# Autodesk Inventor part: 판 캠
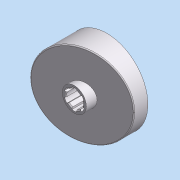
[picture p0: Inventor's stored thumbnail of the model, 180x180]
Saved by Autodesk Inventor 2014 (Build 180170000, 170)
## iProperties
Created: 2012-05
Part Number: 판 캠
Document SubType Name: 모델링
Designer: SeoGD™
Material: 강철
Density: 7.85 g/cm^3
Appearance: 알루미늄 - 평지
Mass: 681.587 g
Surface Area: 331.303 cm^2
Volume: 86.8264 cm^3
변환 표준: STEP AP214IS
파일 이름: C:\Users\SeoGD\Desktop\?쒗뿕\??stp
전처리기: Build: 253, Release: 2010 SP1 - Date: Wed 07/29/2009
전송 단위: 밀리미터
불확실성: 0.01
Author: SeoGD™
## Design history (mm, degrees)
node "작업 평면4"
sketch "스케치1"
  geometry: C1 r 44.5 at (0, 0); 1 further point
  constraints: 1 centre point, 1 coincident
  dimensions: "d25" = 89 diameter of C1
extrude "돌출1" new body sketch "스케치1" distance "d1" = 40; taper "d2" = 0 deg
sketch "스케치2"
  geometry: L1 (-44.5, 15)-(44.5, 38.847); L2 (-44.5, 0)-(-44.5, 40) reference; L3 (-44.5, 40)-(44.5, 40) reference; L4 (44.5, 0)-(44.5, 40) reference; 1 further point
  constraints: 2 end point, 2 point on line
  dimensions: "d26" = 15 distance of L2.start L1.start; "d27" = 75 deg angle of L1 L2
extrude "돌출2" cut sketch "스케치2" stored distance "d5" = 40; taper "d6" = 0 deg
node "작업 평면1"
sketch "스케치3"
  geometry: C1 r 13 at (0, 0); 1 further point
  constraints: 1 centre point, 1 coincident
  dimensions: "d9" = 26 diameter of C1
extrude "돌출3" join sketch "스케치3" distance "d10" = 38; taper "d11" = 0 deg
hole "구멍1" diameter "d14" = 18; stored, may be unused: countersink angle "d18" = 90 deg, drill point angle "d20" = 118 deg; dims "d12" = 10, "d13" = 10, "d15" = 6, "d16" = 4, "d17" = 2, "d19" = 8
feature "쉘2" dims "d29" = 5
sketch "스케치6"
  geometry: C1 r 17.5 at (0, 0); C2 r 14 at (0, 0) reference; 1 further point
  constraints: 1 centre point, 1 coincident
  dimensions: "d28" = 35 diameter of C1
extrude "돌출4" join sketch "스케치6" stored distance "d30" = 38; taper "d31" = 0 deg
fillet "모깎기1" dims "d32" = 3
chamfer "모따기1" distance "d21" = 1; stored, may be unused: second distance "d22" = 2, angle "d23" = 45 deg
sketch "스케치7"
  geometry: L1 (-12.374, 12.374)-(-27.931, 27.931); A1 r 39.5 centre (0, 0) between (-27.931, 27.931) and (0, 39.5) reference; 2 further points
  constraints: 2 end point, 2 point on circle, 1 point on line, 1 vertical alignment, 2 other
  dimensions: "d33" = 45 deg dimension on point (0, 0) L1.start A1.end
feature "리브1" sketch "스케치7" dims "d34" = 5, "d35" = 1, "d36" = 0
fillet "모깎기2" dims "d37" = 3
sketch "스케치8"
  geometry: L1 (2.5, 10.712)-(2.5, 8.646); L2 (-2.5, 10.712)-(-2.5, 8.646); A1 r 11 centre (0, 0) between (2.5, 10.712) and (-2.5, 10.712); A2 r 9 centre (0, 0) between (2.5, 8.646) and (-2.5, 8.646) reference; 1 further point
  constraints: 4 end point, 4 point on circle, 2 parallel, 1 centre point, 1 coincident, 1 vertical
  dimensions: "d41" = 22 diameter of A1; "d42" = 5 distance between parallel lines of L1 L2
extrude "돌출5" cut sketch "스케치8" stored distance "d43" = 38; taper "d44" = 0 deg
fillet "모깎기3" dims "d48" = 1
node "솔리드1"
node "솔리드 본체"
node "곡면 본체"
pattern_circular "원형 패턴1" dims angle "d39" = 360 deg
pattern_circular "원형 패턴2" dims angle "d46" = 360 deg
node "솔리드2"
